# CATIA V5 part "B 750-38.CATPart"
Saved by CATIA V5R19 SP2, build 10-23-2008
Part number: B 750-38
Bounding box of the stored display mesh (mm): x -22.494 to 22.494, y -22.494 to 22.494, z 0 to 161
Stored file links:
  C:\Users\Bora\Desktop\3D Katı model\B serisi\B 750\B 750-38.CATPart
  C:\Program Files\Dassault Systemes\B19\intel_a\reffiles\standard\MetricThickPitch.txt
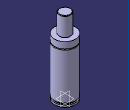
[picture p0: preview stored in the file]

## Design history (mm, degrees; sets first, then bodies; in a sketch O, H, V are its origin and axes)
Body1 (main body)
  Sketch1 on yz-plane, origin (0, 0, 0), H (0, 1, 0), V (0, 0, 1)
    point P3 (12, 160)
    point P5 (12, 160)
    point P7 (22.5, 107.5)
    point P8 (22.5, 105.5)
    point P12 (22.5, 105.5)
    point P13 (22.5, 107.5)
    line L1 (22.5, 0) -> (22.5, 4)
    line L2 (12, 160) -> (12, 121)
    arc A1 centre (11, 160) radius 1 from (12, 160) to (11, 161) ccw
    arc A2 centre (22.5, 106.5) radius 1 from (22.5, 107.5) to (22.5, 105.5) ccw
    line L3 (20, 7.5) -> (20, 4)
    line L4 (22.5, 7.5) -> (22.5, 105.5)
    line L5 (22.5, 107.5) -> (22.5, 121)
    line L6 (11, 161) -> (0, 161)
    point P15 (0, 161)
    line L7 (12, 121) -> (22.5, 121)
    line L8 (0, 0) -> (22.5, 0)
    line L9 (20, 7.5) -> (22.5, 7.5)
    line L10 (20, 4) -> (22.5, 4)
    coincidence: P15 V, P3 P5, P7 P13, P8 P12
    tangency: L6 A1
    horizontal: L7 H, L8 H, L9 H, L10 H
  Shaft1: profile Sketch1, axis Sketch1.V, angle 360
  Sketch2 on face of Shaft1 from Sketch1.L8, origin (0, 0, 0), H (1, 0, 0), V (0, -1, 0)
    point P1 (10, 0)
    distance P1 V = 10
  Hole1: placed by Sketch2, at (10, 0, 0) direction (0, 0, 1), diameter 6.647, depth 13, threaded "M8", thread diameter 8, thread depth 13, pitch 1.25
  CircPattern1: of Hole1, instances 2, angular step 180, axis from xy-plane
